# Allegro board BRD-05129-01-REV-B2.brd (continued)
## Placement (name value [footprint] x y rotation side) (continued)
R726  3.01K  [RESC100X50X40]  80.85 41.61 90 bottom
R727  1.50K  [RESC100X50X40]  84.43 40.43 180 bottom
R728  1.50K  [RESC100X50X40]  84.43 46.51 180 bottom
R729  3.01K  [RESC100X50X40]  80.85 45.36 270 bottom
R730  10.0K  [RESC100X50X40]  68.95 48.62 180 top
R731  10.0K  [RESC100X50X40]  68.95 49.51 0 top
R732  10.0K  [RESC100X50X40]  68.95 56.49 180 top
R733  10.0K  [RESC100X50X40]  68.95 57.38 0 top
R734  10.0K  [RESC100X50X40]  68.95 63.92 180 top
R735  10.0K  [RESC100X50X40]  68.95 64.8 0 top
R736  10.0K  [RESC100X50X40]  68.74 39.79 180 top
R737  10.0K  [RESC100X50X40]  68.74 40.67 0 top
R738  30  [RESC100X50X40]  65.99 47.35 180 bottom
R739  30  [RESC100X50X40]  65.99 46.21 180 bottom
R740  30  [RESC100X50X40]  65.99 41.82 180 bottom
R741  30  [RESC100X50X40]  65.99 42.96 180 bottom
R742  30  [RESC100X50X40]  65.99 55.52 180 bottom
R743  30  [RESC100X50X40]  65.99 54.38 180 bottom
R744  30  [RESC100X50X40]  65.99 49.99 180 bottom
R745  30  [RESC100X50X40]  65.99 51.13 180 bottom
R746  30  [RESC100X50X40]  65.99 63.69 180 bottom
R747  30  [RESC100X50X40]  65.99 62.55 180 bottom
R748  30  [RESC100X50X40]  65.99 58.15 180 bottom
R749  30  [RESC100X50X40]  65.99 59.3 180 bottom
R750  30  [RESC100X50X40]  65.99 39.19 180 bottom
R751  30  [RESC100X50X40]  65.99 38.04 180 bottom
R752  30  [RESC100X50X40]  65.99 33.65 180 bottom
R753  30  [RESC100X50X40]  65.99 34.79 180 bottom
R754  10.0K  [RESC100X50X40]  72.56 23.03 180 bottom
R755  22.0  [RESC100X50X40]  53.32 51.59 135 bottom
R756  22.0  [RESC100X50X40]  53.3 50.72 135 top
R757  22.0  [RESC100X50X40]  53.97 53.16 180 bottom
R758  22.0  [RESC100X50X40]  53.94 52.27 180 top
R759  22.0  [RESC100X50X40]  53.32 54.73 225 bottom
R760  22.0  [RESC100X50X40]  53.3 53.82 225 top
R761  1.00K  [RESC100X50X40]  111.68 39.51 0 bottom
R762  40.2K  [RESC100X50X40]  111.68 40.58 0 bottom
R763  10.0K  [RESC100X50X40]  111.68 41.66 180 bottom
R764  100.0K  [RESC100X50X40]  45.13 18.84 270 bottom
R765  100.0K  [RESC100X50X40]  47.16 17.95 270 top
SW1  B3U-1000P  [SW_OMRON_2P]  3.09 78.96 270 top
SW2  B3U-1000P  [SW_OMRON_2P]  3.09 48.69 270 top
TP1  -  [TP_PAD]  20.37 94.41 0 top
TP2  -  [TP_PAD]  11.58 98.55 0 top
TP3  -  [TP_PAD]  26.97 27.61 180 top
TP4  -  [TP_PAD]  4.87 39.29 0 top
TP5  -  [TP_PAD]  25.83 90.98 0 top
TP6  -  [TP_PAD]  49.2 94.15 180 top
TP7  -  [TP_PAD]  7.29 61.9 90 top
TP8  -  [TP_PAD]  50.85 93.26 180 top
TP9  -  [TP_PAD]  74.15 91.06 270 top
TP10  -  [TP_PAD]  77.9 91.99 90 top
TP11  -  [TP_PAD]  54.79 27.7 180 top
TP12  -  [TP_PAD]  70.73 23.69 90 top
TP13  -  [TP_PAD]  76.88 19.1 0 top
TP14  -  [TP_PAD]  130.54 78.89 90 top
TP15  -  [TP_PAD]  80.31 22.02 180 top
TP37  -  [TP_PAD]  8.3 63.42 270 top
TP38  -  [TP_PAD]  8.3 65.07 0 top
TP39  -  [TP_PAD]  8.3 53.13 0 top
TP40  -  [TP_PAD]  96.95 16.3 0 bottom
TP41  -  [TP_PAD]  126.44 45 270 bottom
TP43  -  [TP_PAD]  117.94 57.95 90 bottom
TP45  -  [TP_PAD]  131.26 63.62 270 bottom
TP47  -  [TP_PAD]  20.37 94.41 180 bottom
TP48  -  [TP_PAD]  26.97 27.61 180 bottom
TP49  -  [TP_PAD]  11.58 98.55 180 bottom
TP50  -  [TP_PAD]  4.87 39.29 180 bottom
TP51  -  [TP_PAD]  25.83 90.98 180 bottom
TP52  -  [TP_PAD]  49.2 94.15 180 bottom
TP53  -  [TP_PAD]  7.29 61.9 180 bottom
TP54  -  [TP_PAD]  50.85 93.26 180 bottom
TP55  -  [TP_PAD]  74.15 91.06 180 bottom
TP56  -  [TP_PAD]  77.9 91.99 180 bottom
TP57  -  [TP_PAD]  54.79 27.7 180 bottom
TP58  -  [TP_PAD]  70.73 23.69 180 bottom
TP59  -  [TP_PAD]  76.88 19.1 180 bottom
TP60  -  [TP_PAD]  130.54 78.89 180 bottom
TP61  -  [TP_PAD]  80.31 22.02 180 bottom
TP62  -  [TP_PAD]  18.48 61.51 180 bottom
TP63  -  [TP_PAD]  18.5 60.24 180 bottom
TP64  -  [TP_PAD]  18.59 58.91 180 bottom
TP65  -  [TP_PAD]  18.59 57.58 180 bottom
U1  MPM3840GQV-Z  [PQFN20_MPS_MPM3840GQV]  4.82 55.93 0 bottom
U3  MPM3810AGQB-Z  [QFN12_MPM3805A]  36.06 82.65 270 bottom
U5  MPM3810AGQB-Z  [QFN12_MPM3805A]  26.16 83.69 0 bottom
U6  MP8772  [QFN40P300X300X100-16_MP8772]  17.59 23.99 90 bottom
U7  MP2002A  [DFN300X200X100-8]  6.81 43.53 90 bottom
U8  MP2002A  [DFN300X200X100-8]  75.4 86.18 270 bottom
U9  MP2002A  [DFN300X200X100-8]  60.08 28.49 0 bottom
U11  MP2002A  [DFN300X200X100-8]  41.75 14.97 0 bottom
U12  MP2002A  [DFN300X200X100-8]  63.53 75.26 180 bottom
U13  TPS3430WDRCR  [VSON-CLIP11_3X3MM]  3.65 87.36 90 bottom
U14  INA260  [TSSOP065P620X120_16]  3.96 74.64 90 bottom
U15  M24C64-DRDW8  [TSSOP8_65P440X300MM]  34.17 24.21 90 bottom
U16  PCA9306DCTR  [DCT_R_PDSO_G8]  29.27 25.5 180 top
U19  SLG  [STQFN04P400X400X60_32_270]  34.09 41.67 90 bottom
U22  SN74AVC4T245  [QFN_RSV_16]  38.59 28.66 180 bottom
U24  FT4232HL_LQFP64  [LQFP_64]  55.11 17.71 90 bottom
U25  SN74AVC2T245  [QFN40P140X180X55-10]  48.97 24.75 90 top
U26  93LC56B  [SOIC8P127W390]  66.93 17.86 90 bottom
U37  USB3320  [QFN05P500X500X100_32P_330EP]  43.62 76.96 0 bottom
U38  USB2244-AEZG-06  [QFN05P600X600X85-36_410]  30.88 96.71 0 bottom
U41  MP5016HGQH-Z  [PQFN10_MP5016HGQH]  16.4 96.03 180 top
U42  STMPS2161STR  [SOT95P280X145_5]  4.36 12.75 0 top
U43  USB5744  [VQFN40P700X700X100-56_460EP]  63.78 91.51 0 bottom
U44  GSB311231HR  [CONN_USB_DUAL_GSB311231HR]  49.51 105.52 270 top
U45  MP62341DH-LF-Z  [MSOP8E65P490X110]  39.54 94.77 90 bottom
U64  SN74AVC2T245  [QFN40P140X180X55-10]  43.72 26.08 90 bottom
U66  TPD4E05U06DQAR  [DQA_R_PSON_N10]  44.62 98.09 0 bottom
U67  TPD4E05U06DQAR  [DQA_R_PSON_N10]  52.86 98.41 0 bottom
U82  TPD6E004RSER  [UQFN_8]  30.81 107.44 90 bottom
U89  26MHZ  [OSC_RAL_500X320X154]  4.86 66.13 90 bottom
U91  NB3V1104CDTR2G  [TSSOP8_65P450X310X120]  74.81 80.66 0 bottom
U92  25.000MHz  [OSC_330X260X120_4_RAL]  66.19 79.89 0 bottom
U94  TCAN1043A  [SOIC14_SOT23-THIN_14_DUAL]  110.43 103.54 0 top
U95  ISOW1432BDFMR  [SOIC127P1283X750X355-20]  117.19 88.17 270 top
U96  MP2002A  [DFN300X200X100-8]  54.66 75.94 180 bottom
U97  MPM3810AGQB-Z  [QFN12_MPM3805A]  69.11 26 270 bottom
U98  ADIN1300BCPZ  [LFCSP50P600X600X75_40]  63.78 91.51 180 top
U99  ADIN1300BCPZ  [LFCSP50P600X600X75_40]  96.69 86.15 0 bottom
U100  M24C64-DRDW8  [TSSOP8_65P440X300MM]  54.98 71.36 0 bottom
U101  ADIN1300BCPZ  [LFCSP50P600X600X75_40]  96.69 86.15 180 top
U102  LM5106MM  [VSSOP50P490X110-10]  106.6 37 90 top
U103  LM5106MM  [VSSOP50P490X110-10]  106.6 53.89 90 top
U104  LM5106MM  [VSSOP50P490X110-10]  106.09 70.79 90 top
U105  INA241XX  [SOT23_290X160X110_8]  123.31 38.15 270 bottom
U106  INA241XX  [SOT23_290X160X110_8]  123.95 48.18 270 bottom
U107  INA241XX  [SOT23_290X160X110_8]  123.95 57.32 270 bottom
U108  AD7352  [TSSOP065P620X120_16]  60.86 44.59 180 bottom
U109  SN74AVC4T245  [QFN_RSV_16]  49.71 52.75 270 bottom
U110  AD7352  [TSSOP065P620X120_16]  60.86 52.75 180 bottom
U111  SN74AVC4T245  [QFN_RSV_16]  49.71 46.69 270 bottom
U112  AD7352  [TSSOP065P620X120_16]  60.86 60.92 180 bottom
U113  INA241XX  [SOT23_290X160X110_8]  112.28 26.91 90 bottom
U114  AD7352  [TSSOP065P620X120_16]  60.86 36.42 180 bottom
U115  SN74AVC4T245  [QFN_RSV_16]  52.37 41.3 270 bottom
U116  TXU0104PWR  [TSSOP65P440X500X120_14]  124.62 71.94 180 top
U117  AM26LV32E  [SOIC127P600X175-16]  121.84 92.63 0 bottom
U118  SN74AVC2T245  [QFN40P140X180X55-10]  84.59 17 90 bottom
U119  AD7797B  [TSSOP065P620X120_16]  91.99 14.51 180 bottom
U120  SN74AVC2T245  [QFN40P140X180X55-10]  80.28 16.88 90 bottom
U121  UCC27516DRS  [SON95P300X300X80-6TP]  107.12 15.52 270 top
U122  MP2002A  [DFN300X200X100-8]  72.89 16.63 180 bottom
U123  TLV9102IDDFR  [SOT65P280X280X110-8]  70.76 47.93 90 bottom
U124  TLV9102IDDFR  [SOT65P280X280X110-8]  70.76 55.8 90 bottom
U125  TLV9102IDDFR  [SOT65P280X280X110-8]  70.76 63.23 90 bottom
U127  LTC6362IDD#PBF  [DFN300X300X80-8]  75.99 51.87 90 bottom
U128  LTC6362IDD#PBF  [DFN300X300X80-8]  83.23 52.17 90 bottom
U129  LTC6362IDD#PBF  [DFN300X300X80-8]  75.99 60.81 90 bottom
U130  LTC6362IDD#PBF  [DFN300X300X80-8]  83.23 61.12 90 bottom
U131  LTC6362IDD#PBF  [DFN300X300X80-8]  75.99 69.76 90 bottom
U132  LTC6362IDD#PBF  [DFN300X300X80-8]  83.23 70.07 90 bottom
U133  LTC6362IDD#PBF  [DFN300X300X80-8]  75.99 42.92 90 bottom
U134  LTC6362IDD#PBF  [DFN300X300X80-8]  83.23 43.48 90 bottom
U135  TLV9102IDDFR  [SOT65P280X280X110-8]  120.82 42.41 180 bottom
U136  TLV9102IDDFR  [SOT65P280X280X110-8]  124.63 62.02 180 bottom
U137  TLV9102IDDFR  [SOT65P280X280X110-8]  70.55 39.1 90 bottom
X1  TPD4S012  [DRY_6_SON]  55.85 8 0 top
X2  12.00MHZ  [XTAL_320X250X71]  61.93 9.2 0 bottom
X5  TPD4S012  [DRY_6_SON]  49.73 98.09 0 bottom
X6  TPD4S012  [DRY_6_SON]  47.42 98.09 0 bottom
X11  24.00MHZ  [XTAL_EPSON_FA238]  31.19 88.4 180 bottom
X12  24.00MHZ  [XTAL_EPSON_FA238]  47.54 69.22 180 bottom
X13  25MHZ  [XTAL_EPSON_FA238]  59.58 82.05 0 bottom
X14  25.00MHZ  [XTAL_ABM8]  73.59 94.51 0 top
Z1  -  [0201_SHORT]  15.15 19.98 0 bottom
Z4  -  [0201_SHORT]  33.69 83.75 270 bottom
Z5  -  [0201_SHORT]  25.06 81.32 0 bottom
Z6  -  [0201_SHORT]  66.35 26.97 270 bottom

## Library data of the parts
C1-C3 C6 C26 C30-C35 C311 C312 = CAP_NP: signal model: DEFAULT_CAPACITOR_2.2e+07pF_2_1
C4 C353 C354 = CAP_NP: alternate symbols: (CAPC200X125X125RND); signal model: DEFAULT_CAPACITOR_4.7e+07pF_2_1
C5 C103 C104 = CAP_NP: alternate symbols: (CAPC100X50X55RND); signal model: DEFAULT_CAPACITOR_27.000000pF_2_1
C7 C8 C24 C25 = CAP_NP: alternate symbols: (0603); signal model: DEFAULT_CAPACITOR_2.2e+07pF_2_1
C14 C21 C27 C41 C44 C295-C298 = CAP_NP: alternate symbols: (CAPC100X50X55RND); signal model: DEFAULT_CAPACITOR_1000pF_2_1
C16 C17 C22 C23 C28 C29 C42 C43 C78 C79 C203 C204 C272 C274 = CAP_NP: signal model: DEFAULT_CAPACITOR_1e+07pF_2_1
C36 C37 C49 C50 C53 C64 C75 C80 C81 C83 C84 C87 C88 C90-C94 C96-C102 C105 C175 C176 C207 C209 C210 C234 C236 C237 C273 C275-C277 C279-C286 C289-C292 C299 C300 C303 C304 C309 C310 C315-C317 C324 C329 = CAP_NP: alternate symbols: (CAPC100X50X55RND); signal model: DEFAULT_CAPACITOR_100000pF_2_1
C38 C51 C89 C205 C208 C238 C323 = CAP_NP: alternate symbols: (CAPC100X50X55RND); signal model: DEFAULT_CAPACITOR_1e+06pF_2_1
C39 = CAP_NP: alternate symbols: (CAPC100X50X55RND); signal model: DEFAULT_CAPACITOR_56.000000pF_2_1
C40 = CAP_NP: signal model: DEFAULT_CAPACITOR_22000pF_2_1
C52 = CAP_NP: alternate symbols: ((0402,C402-25,CAPC100X50X55L25NRND,CAPC100X50X55L30NRND,CAPC100X50X55L30N)); signal model: DEFAULT_CAPACITOR_220000pF_2_1
C73 = CAP_NP: alternate symbols: (CAPC100X50X55RND); signal model: DEFAULT_CAPACITOR_100.000000pF_2_1
C82 C85 C95 = CAP_NP: alternate symbols: (CAPC100X50X60RND); signal model: DEFAULT_CAPACITOR_4.7e+06pF_2_1
C206 = CAP_NP: signal model: DEFAULT_CAPACITOR_47000pF_2_1
C235 = CAP_NP: alternate symbols: (CAPC100X50X55RND); signal model: DEFAULT_CAPACITOR_39.000000pF_2_1
C278 = CAP_NP: alternate symbols: (CAPC100X50X55RND); signal model: DEFAULT_CAPACITOR_2.2e+06pF_2_1
C319 = CAP_NP: alternate symbols: ((0402,C402-25,CAPC100X50X55L25NRND,CAPC100X50X55L30NRND,CAPC100X50X55L30N)); signal model: DEFAULT_CAPACITOR_6800pF_2_1
C344 = CAP_NP: alternate symbols: (CAPC100X50X56RND); signal model: DEFAULT_CAPACITOR_33.000000pF_2_1
C369 C548 C558-C565 C568 C569 C581 C582 C589 C591 C592 C598-C603 C606-C609 C612 C619-C629 C631 C632 C634-C638 C640 C642 C645-C652 C654-C656 C658 C659 C661-C663 C665-C674 C676-C678 C680 C681 C683-C685 C687 C693-C695 C701 C702 C708-C715 C717-C720 C722 C723 C725 C726 C728 C729 C731-C734 C736-C738 C741-C743 C745-C747 C753-C756 C758 C759 C761-C769 C771-C783 C785 C788 C789 C793-C825 = CAP_NP: alternate symbols: (CAPC100X50X55RND)
C370 C371 = CAP_NP: alternate symbols: (CAPC100X50X56RND)
C372-C380 C688 C696 C703 C828 C829 = CAP_NP: alternate symbols: ((0402,C402-25,CAPC100X50X55L25NRND,CAPC100X50X55L30NRND,CAPC100X50X55L30N))
C387 C604 C605 C610 C611 C613-C618 C630 C633 C641 C653 C657 C660 C675 C679 C682 C689-C692 C697-C700 C704-C707 C716 C721 C724 C727 C730 C735 C739 C740 C744 C748-C750 C752 C757 C760 C770 C784 C786 C787 C826 C827 = CAP_NP
C557 C574 = CAP_NP: alternate symbols: (CAPC100X50X60RND)
C566 C567 C643 C644 = CAP_NP: alternate symbols: (CAPC100X50X50RND)
C751 = CAP_P
D1 D12 = DIODE_ZENER
D2 = BAT54T1G
D3-D5 = MBRS260T3G
D15-D20 = TVS_RCLAMP0502BATCT
D21 = DIODE_TVS_UDIR
D22 D23 = TVS_SM712-02HTG
D24 D25 = SCHOTTKY_DIODE
DS1-DS10 = LED
F1 = ITV5432
J1 J19-J21 J44 = HDR_1X3
J2 = HDR_2X6
J3 = HDR_2X7
J4 = CONN_USB_MICRO_B_TH
J11 = 5025700893
J12 = PJ-202AH
J13 = HDR_REMOTE_SENSE_A: signal model: DEFAULT_RESISTOR_22.000000OHM_2_1
J15-J17 J26 J28 J30 J40 J41 = TP-HOOK: alternate symbols: (TP_KEY_MINI_DNP)
J18 J46 J47 = EM_3PIN
J22 J45 = EM1935187_ST
J23 J51 = HDR_1X2
J24 = HFJ11_1G01E_L12RL
J25 = 0879-2C1R-54
J27 J29 J31 J52-J54 = TEST_LOOP_5016
J32 = MR60PB-M
J39 = XT60PT-M
J42 = SHROUDED_HDR_1X6
J43 = HDR_2X5
JA1 = SAMTEC-ADx6-60X4
JA3 = SAMTEC-ADx6-10X4
L1 = IND: signal model: DEFAULT_INDUCTOR_1200nH_2_1
L2-L5 L8-L17 = IND
MH1-MH10 = HOLE
Q5 = IRFHS8342
Q6-Q10 Q12 Q13 Q17 Q19-Q23 Q26-Q34 Q37 Q43-Q48 = DMN26D0UFB4
Q18 = FET-3PIN
Q24 Q25 = FDN304P
Q35 Q36 Q38-Q42 = FET_NCH_DFN5
R1 R54 R219 R220 = RES: signal model: DEFAULT_RESISTOR_200000OHM_2_1
R2 = RES: alternate symbols: (0402); signal model: DEFAULT_RESISTOR_44200OHM_2_1
R4 R5 R7 R28 = RES: signal model: DEFAULT_RESISTOR_100000OHM_2_1
R6 R17 R23 R29 R38 R40 R41 R45-R51 R74 R76 R77 R209 R210 R218 R233-R235 R241 R260-R263 = RES: alternate symbols: (RESC100X50X40RND); signal model: DEFAULT_RESISTOR_10000OHM_2_1
R14 = RES: signal model: DEFAULT_RESISTOR_68000OHM_2_1
R16 = RES: alternate symbols: ((0402,C402-25,RESC100X50X40L25NRND)); signal model: DEFAULT_RESISTOR_34000OHM_2_1
R21 R26 = RES: alternate symbols: (RESC100X50X40RND); signal model: DEFAULT_RESISTOR_40200OHM_2_1
R24 = RES: alternate symbols: (RESC100X50X40RND); signal model: DEFAULT_RESISTOR_26100OHM_2_1
R27 = RES: alternate symbols: (RESC100X50X40RND); signal model: DEFAULT_RESISTOR_45300OHM_2_1
R30 = RES: alternate symbols: (RESC100X50X40RND); signal model: DEFAULT_RESISTOR_20000OHM_2_1
R31 = RES: alternate symbols: ((0402,C402-25,RESC100X50X40L25NRND)); signal model: DEFAULT_RESISTOR_2700OHM_2_1
R32 R75 R256 = RES: alternate symbols: (RESC100X50X40RND); signal model: DEFAULT_RESISTOR_1000.000000OHM_2_1
R33 = RES: signal model: DEFAULT_RESISTOR_0.001OHM_2_1
R34 = RES: alternate symbols: (RESC60X30X26RND); signal model: DEFAULT_RESISTOR_100000OHM_2_1
R36 R39 = RES: signal model: DEFAULT_RESISTOR_56200OHM_2_1
R44 R66 R222 = RES: alternate symbols: (RESC100X50X40RND); signal model: DEFAULT_RESISTOR_0.001OHM_2_1
R55 R56 = RES: alternate symbols: ((0402,C402-25,RESC100X50X40L25NRND)); signal model: DEFAULT_RESISTOR_2210OHM_2_1
R58 R61 R63 R64 R452 R466 R467 R473 R474 R517 R518 R520 R522 R524 R525 R536 R537 R540 R563 R564 R592 R593 R617 R626 R632 R638-R642 R647 R648 R651 R652 R659-R661 R684 R707 R708 R711 R712 R715 R716 R719 R720 R723 R724 R727 R728 R738-R753 = RES
R78 = RES: alternate symbols: (RESC100X50X40RND); signal model: DEFAULT_RESISTOR_2000OHM_2_1
R79 R221 = RES: alternate symbols: (RESC100X50X40RND); signal model: DEFAULT_RESISTOR_12000OHM_2_1
R130 = RES: alternate symbols: (RESC100X50X40RND); signal model: DEFAULT_RESISTOR_4700OHM_2_1
R133 = RES: alternate symbols: ((0402,C402-25,RESC100X50X40L25NRND)); signal model: DEFAULT_RESISTOR_300000OHM_2_1
R134 = RES: signal model: DEFAULT_RESISTOR_274000OHM_2_1
R135 = RES: signal model: DEFAULT_RESISTOR_422.000000OHM_2_1
R157-R161 R254 = RES: alternate symbols: (RESC100X50X40RND); signal model: DEFAULT_RESISTOR_261.000000OHM_2_1
R162-R165 = RES: alternate symbols: (RESC100X50X40RND); signal model: DEFAULT_RESISTOR_499.000000OHM_2_1
R166 R167 R243 = RES: alternate symbols: (RESC100X50X40RND); signal model: DEFAULT_RESISTOR_100000OHM_2_1
R213 = RES: alternate symbols: (RESC100X50X40RND); signal model: DEFAULT_RESISTOR_8060OHM_2_1
R223 = RES: signal model: DEFAULT_RESISTOR_1.000000OHM_2_1
R248-R253 = RES: signal model: DEFAULT_CAPACITOR_100000pF_2_1
R264 = RES: alternate symbols: (RESC100X50X40RND); signal model: DEFAULT_RESISTOR_20.000000OHM_2_1
R265 = RES: alternate symbols: (RESC60X30X26RND)
R266 R267 R619 R621 R628 R629 R634 R635 R764 R765 = RES: alternate symbols: (0402)
R274 R275 R294 R295 R428 R429 R446-R451 R463-R465 R468 R469 R471 R472 R477-R480 R494 R495 R500 R501 R507 R514-R516 R519 R521 R523 R526-R534 R538 R541-R561 R565 R567-R578 R581-R590 R594 R596-R616 R618 R620 R623-R625 R627 R630 R631 R633 R636 R637 R643 R646 R649 R650 R653 R656 R662 R663 R667 R669-R683 R685 R754 R761-R763 = RES: alternate symbols: (RESC100X50X40RND)
R276-R283 = RES: alternate symbols: (RESC100X50X40RND); signal model: DEFAULT_CAPACITOR_100000pF_2_1
R462 R539 R566 R579 R580 R595 R622 R664-R666 R668 R702-R706 R709 R710 R713 R714 R717 R718 R721 R722 R725 R726 R729-R737 = RES: alternate symbols: ((0402,C402-25,RESC100X50X40L25NRND))
R755-R760 = RES: alternate symbols: ((0402,C402-25,RESC100X50X40L25NRND)); signal model: RES_RESC100X50X40_22.0_(0402_C402-25_RESC100X50X40L25NRND)_22.0
SW1 SW2 = BTN_MOMENT
TP1-TP15 TP37-TP41 TP43 TP45 TP47-TP65 = TP
U1 = MPM3840
U3 U5 U97 = MPM3810A
U6 = MP8771: alternate symbols: (QFN40P300X300X100-16)
U7-U9 U11 U12 U96 U122 = MP8904: alternate symbols: (QFN_MP8904DD_8)
U13 = TPS3430
U14 = INA260AIPW
U15 U100 = M24C64
U16 = PCA9306DCTR
U19 = SLG
U22 U109 U111 U115 = SN74AVC4T245
U24 = FT4232HL
U25 U64 U118 U120 = SN74AVC2T245
U26 = 93LC56B
U37 = USB3320_QFN32
U38 = USB2244
U41 = MP5016H
U42 = TPS2065CDBVT
U43 = USB5744
U44 = GSB311231HR
U45 = MP62341DH
U66 U67 = TPD4E05U06DQAR
U82 = TPD6E004RSER
U89 = XCO583IV11-27.000
U91 = NB3V1104CDTR2G
U92 = SIT_4PIN
U94 = TCAN1043A
U95 = ISOW1432BDFMR
U98 U99 U101 = ADIN1300BCPZ
U102-U104 = LM5106MM
U105-U107 U113 = INA241XX
U108 U110 U112 U114 = AD7352
U116 = TXU0104PWR
U117 = AM26LV32E
U119 = AD7797B
U121 = UCC27516DRS
U123-U125 U135-U137 = TLV9102IDDF
U127-U134 = LTC6362
X1 X5 X6 = TPD4S012
X2 X14 = ABM8_XTAL
X11 X12 = FA-238A_XTAL
X13 = FA238
Z1 Z4-Z6 = 0201_SHORT

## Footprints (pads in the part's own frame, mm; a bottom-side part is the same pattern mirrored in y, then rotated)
0201_SHORT
  rect 0.381x0.381 smd: 1(-0.292,0)
  custom 0.089x0.089 smd: 2(0.292,0)
87832_1420
  round 1.016 hole 1.016 unplated: (-5,0) (5,0)
  rect 1x2.75 smd: 1(-6,-2.125) 2(-6,2.125) 3(-4,-2.125) 4(-4,2.125) 5(-2,-2.125) 6(-2,2.125) 7(0,-2.125) 8(0,2.125) 9(2,-2.125) 10(2,2.125) 11(4,-2.125) 12(4,2.125) 13(6,-2.125) 14(6,2.125)
AMASS_XT60PW-M
  rect 3.7x3.7 hole 2.692: 1(0,0)
  round 3.7 hole 2.692: 2(-7.2,0)
  oval 1.2x2.7 hole 0.6x1.7: M1(3.15,6) M2(-10.35,6)
BEL_0879-2C1R-54
  round 3.25 hole 3.251 unplated: (-2.407,-4.699) (9.023,-4.699)
  round 2.51 hole 1.575: 1(-5.199,10.791) 2(-5.197,-9.269) 3(11.813,-9.269) 4(11.813,6.731)
  round 1.5 hole 0.889: P1_L(0,0) P1_U(6.61,0) P2_L(1.27,1.27) P2_U(5.34,1.27) P3_L(0,2.54) P3_U(6.61,2.54) P4_L(1.27,3.81) P4_U(5.34,3.81) P5_L(0,5.08) P5_U(6.61,5.08) P6_L(1.27,6.35) P6_U(5.34,6.35) P7_L(0,7.62) P7_U(6.61,7.62) P8_L(1.27,8.89) P8_U(5.34,8.89) P9_L(0,10.16) P9_U(6.61,10.16) P10_L(1.276,11.43) P10_U(5.34,11.43)
  round 1.52 hole 1.016: P11_L2_U(-3.677,7.091) P11_L4_L(-3.677,-7.599) P12_L2_U(-3.677,0.741) P12_L4_L(-1.137,-7.599) P13_L1_U(10.294,3.281) P13_L3_L(7.753,-7.599) P14_L1_U(10.294,0.741) P14_L3_L(10.293,-7.599)
CAPC100X50X50
  rect 0.5x0.51 smd: 1(-0.45,0) 2(0.45,0)
CAPC100X50X55
  rect 0.5x0.51 smd: 1(-0.45,0) 2(0.45,0)
CAPC100X50X56
  rect 0.5x0.51 smd: 1(-0.45,0) 2(0.45,0)
CAPC100X50X60
  rect 0.5x0.51 smd: 1(-0.45,0) 2(0.45,0)
CAPC100X50X70
  rect 0.5x0.51 smd: 1(-0.45,0) 2(0.45,0)
CAPC160X80X100
  rect 0.71x0.81 smd: 1(-0.645,0) 2(0.645,0)
CAPC200X125X125
  rect 0.98x1.32 smd: 1(-0.78,0) 2(0.78,0)
CAPC200X125X145
  rect 0.98x1.32 smd: 1(-0.78,0) 2(0.78,0)
CAPC620X540X280
  rect 1.27x5.654 smd: 1(-2.687,0) 2(2.687,0)
CAPE_1250X2000
  rect 1.524x1.524 hole 0.914: 1(0,0)
  round 1.524 hole 0.914: 2(5,0)
CON_AMASS_MR60PB-M
  rect 4.6x4.6 hole 3.404: 1(0,0)
  round 4.6 hole 3.404: 2(5.5,0) 3(11,0)
CON_CUI_PJ202AH
  oval 1.5x4.6 hole 1.016x3.505: 1(0,0)
  oval 1.5x3.8 hole 1.016x2.997: 2(6,0)
  oval 3.8x1.5 hole 2.997x1.016: 3(3,4.7)
CON_ETH_HFJ111G01E_L12RL
  round 3.25 hole 3.251 unplated: (-5.715,0) (5.715,0)
  round 1.27 hole 0.889: 1(-5.715,8.89) 2(-4.445,6.35) 3(-3.175,8.89) 4(-1.905,6.35) 5(-0.635,8.89) 6(0.635,6.35) 7(1.905,8.89) 8(3.175,6.35) 9(4.445,8.89) 10(5.715,6.35)
  round 1.52 hole 1.016: 11(-6.629,-4.064) 12(-4.089,-4.064) 13(4.089,-4.064) 14(6.629,-4.064)
  round 2.1 hole 1.6: 15(-7.747,3.048) 16(7.747,3.048)
CON_EUROMAG_ST_4_5MM
  rect 2.2x2.2 hole 1.422: 1(0,0)
  round 2.2 hole 1.422: 2(0,-5) 3(0,-10) 4(0,-15)
CON_HR_ZX62D_AB_5P8
  rect 0.4x1.35 smd: 1(-1.3,0) 2(-0.65,0) 3(0,0) 4(0.65,0) 5(1.3,0)
  oval 1.23x1.9 hole 0.813x1.499: 6(4.089,-2.802) 9(-4.089,-2.802)
  rect 1.8x1.9 smd: 7(1.156,-2.802) 8(-1.156,-2.802)
  oval 1.05x1.25 hole 0.66x0.838: 10(-2.226,0.323) 11(2.226,0.323)
CON_MOL_10P_5025700893
  rect 0.8x1.5 smd: 1(0,0) 2(1.1,0) 3(2.2,0) 4(3.3,0) 5(4.4,0) 6(5.5,0) 7(6.6,0) 8(7.7,0)
  rect 1.4x1.7 smd: 9(-3.747,2.896) 10(9.157,2.896)
  rect 1.15x1.5 smd: 11(9.157,-6.871)
  rect 1.5x1.15 smd: 12(8.712,-11.582) 13(2.095,-11.582) 14(-0.191,-11.582)
CON_SAMTEC_ADM6_10_4
  round 0.95 hole 0.95 unplated: (-4.26,1.27) (4.26,0)
  round 0.356 smd: A1(2.857,1.75) A2(2.223,1.75) A3(1.587,1.75) A4(0.953,1.75) A5(0.318,1.75) A6(-0.318,1.75) A7(-0.953,1.75) A8(-1.587,1.75) A9(-2.223,1.75) A10(-2.857,1.75) B1(2.857,0.79) B2(2.223,0.79) B3(1.587,0.79) B4(0.953,0.79) B5(0.318,0.79) B6(-0.318,0.79) B7(-0.953,0.79) B8(-1.587,0.79) B9(-2.223,0.79) B10(-2.857,0.79) C1(2.857,-0.79) C2(2.223,-0.79) C3(1.587,-0.79) C4(0.953,-0.79) C5(0.318,-0.79) C6(-0.318,-0.79) C7(-0.953,-0.79) C8(-1.587,-0.79) C9(-2.223,-0.79) C10(-2.857,-0.79) D1(2.857,-1.75) D2(2.223,-1.75) D3(1.587,-1.75) D4(0.953,-1.75) D5(0.318,-1.75) D6(-0.318,-1.75) D7(-0.953,-1.75) D8(-1.587,-1.75) D9(-2.223,-1.75) D10(-2.857,-1.75)
CON_SAMTEC_ADM6_60_4
  round 0.95 hole 0.95 unplated: (-20.135,1.27) (20.135,0)
  round 0.356 smd: A1(18.733,1.75) A2(18.098,1.75) A3(17.462,1.75) A4(16.828,1.75) A5(16.192,1.75) A6(15.557,1.75) A7(14.922,1.75) A8(14.287,1.75) A9(13.652,1.75) A10(13.018,1.75) A11(12.383,1.75) A12(11.748,1.75) A13(11.113,1.75) A14(10.477,1.75) A15(9.842,1.75) A16(9.207,1.75) A17(8.572,1.75) A18(7.938,1.75) A19(7.303,1.75) A20(6.668,1.75) A21(6.032,1.75) A22(5.397,1.75) A23(4.763,1.75) A24(4.128,1.75) A25(3.493,1.75) A26(2.857,1.75) A27(2.223,1.75) A28(1.587,1.75) A29(0.953,1.75) A30(0.318,1.75) A31(-0.318,1.75) A32(-0.953,1.75) A33(-1.587,1.75) A34(-2.223,1.75) A35(-2.857,1.75) A36(-3.493,1.75) A37(-4.128,1.75) A38(-4.763,1.75) A39(-5.397,1.75) A40(-6.032,1.75) A41(-6.668,1.75) A42(-7.303,1.75) A43(-7.938,1.75) A44(-8.572,1.75) A45(-9.207,1.75) A46(-9.842,1.75) A47(-10.477,1.75) A48(-11.113,1.75) A49(-11.748,1.75) A50(-12.383,1.75) A51(-13.018,1.75) A52(-13.652,1.75) A53(-14.287,1.75) A54(-14.922,1.75) A55(-15.557,1.75) A56(-16.192,1.75) A57(-16.828,1.75) A58(-17.462,1.75) A59(-18.098,1.75) A60(-18.733,1.75) B1(18.733,0.79) B2(18.098,0.79) B3(17.462,0.79) B4(16.828,0.79) B5(16.192,0.79) B6(15.557,0.79) B7(14.922,0.79) B8(14.287,0.79) B9(13.652,0.79) B10(13.018,0.79) B11(12.383,0.79) B12(11.748,0.79) B13(11.113,0.79) B14(10.477,0.79) B15(9.842,0.79) B16(9.207,0.79) B17(8.572,0.79) B18(7.938,0.79) B19(7.303,0.79) B20(6.668,0.79) B21(6.032,0.79) B22(5.397,0.79) B23(4.763,0.79) B24(4.128,0.79) B25(3.493,0.79) B26(2.857,0.79) B27(2.223,0.79) B28(1.587,0.79) B29(0.953,0.79) B30(0.318,0.79) B31(-0.318,0.79) B32(-0.953,0.79) B33(-1.587,0.79) B34(-2.223,0.79) B35(-2.857,0.79) B36(-3.493,0.79) B37(-4.128,0.79) B38(-4.763,0.79) B39(-5.397,0.79) B40(-6.032,0.79) B41(-6.668,0.79) B42(-7.303,0.79) B43(-7.938,0.79) B44(-8.572,0.79) B45(-9.207,0.79) B46(-9.842,0.79) B47(-10.477,0.79) B48(-11.113,0.79) B49(-11.748,0.79) B50(-12.383,0.79) B51(-13.018,0.79) B52(-13.652,0.79) B53(-14.287,0.79) B54(-14.922,0.79) B55(-15.557,0.79) B56(-16.192,0.79) B57(-16.828,0.79) B58(-17.462,0.79) B59(-18.098,0.79) B60(-18.733,0.79) C1(18.733,-0.79) C2(18.098,-0.79) C3(17.462,-0.79) C4(16.828,-0.79) C5(16.192,-0.79) C6(15.557,-0.79) C7(14.922,-0.79) C8(14.287,-0.79) C9(13.652,-0.79) C10(13.018,-0.79) C11(12.383,-0.79) C12(11.748,-0.79) C13(11.113,-0.79) C14(10.477,-0.79) C15(9.842,-0.79) C16(9.207,-0.79) C17(8.572,-0.79) C18(7.938,-0.79) C19(7.303,-0.79) C20(6.668,-0.79) C21(6.032,-0.79) C22(5.397,-0.79) C23(4.763,-0.79) C24(4.128,-0.79) C25(3.493,-0.79) C26(2.857,-0.79) C27(2.223,-0.79) C28(1.587,-0.79) C29(0.953,-0.79) C30(0.318,-0.79) C31(-0.318,-0.79) C32(-0.953,-0.79) C33(-1.587,-0.79) C34(-2.223,-0.79) C35(-2.857,-0.79) C36(-3.493,-0.79) C37(-4.128,-0.79) C38(-4.763,-0.79) C39(-5.397,-0.79) C40(-6.032,-0.79) C41(-6.668,-0.79) C42(-7.303,-0.79) C43(-7.938,-0.79) C44(-8.572,-0.79) C45(-9.207,-0.79) C46(-9.842,-0.79) C47(-10.477,-0.79) C48(-11.113,-0.79) C49(-11.748,-0.79) C50(-12.383,-0.79) C51(-13.018,-0.79) C52(-13.652,-0.79) C53(-14.287,-0.79) C54(-14.922,-0.79) C55(-15.557,-0.79) C56(-16.192,-0.79) C57(-16.828,-0.79) C58(-17.462,-0.79) C59(-18.098,-0.79) C60(-18.733,-0.79) D1(18.733,-1.75) D2(18.098,-1.75) D3(17.462,-1.75) D4(16.828,-1.75) D5(16.192,-1.75) D6(15.557,-1.75) D7(14.922,-1.75) D8(14.287,-1.75) D9(13.652,-1.75) D10(13.018,-1.75) D11(12.383,-1.75) D12(11.748,-1.75) D13(11.113,-1.75) D14(10.477,-1.75) D15(9.842,-1.75) D16(9.207,-1.75) D17(8.572,-1.75) D18(7.938,-1.75) D19(7.303,-1.75) D20(6.668,-1.75) D21(6.032,-1.75) D22(5.397,-1.75) D23(4.763,-1.75) D24(4.128,-1.75) D25(3.493,-1.75) D26(2.857,-1.75) D27(2.223,-1.75) D28(1.587,-1.75) D29(0.953,-1.75) D30(0.318,-1.75) D31(-0.318,-1.75) D32(-0.953,-1.75) D33(-1.587,-1.75) D34(-2.223,-1.75) D35(-2.857,-1.75) D36(-3.493,-1.75) D37(-4.128,-1.75) D38(-4.763,-1.75) D39(-5.397,-1.75) D40(-6.032,-1.75) D41(-6.668,-1.75) D42(-7.303,-1.75) D43(-7.938,-1.75) D44(-8.572,-1.75) D45(-9.207,-1.75) D46(-9.842,-1.75) D47(-10.477,-1.75) D48(-11.113,-1.75) D49(-11.748,-1.75) D50(-12.383,-1.75) D51(-13.018,-1.75) D52(-13.652,-1.75) D53(-14.287,-1.75) D54(-14.922,-1.75) D55(-15.557,-1.75) D56(-16.192,-1.75) D57(-16.828,-1.75) D58(-17.462,-1.75) D59(-18.098,-1.75) D60(-18.733,-1.75)
CONN_USB_DUAL_GSB311231HR
  round 1.1 hole 0.711: 1(-1.5,3.5) 2(-1.5,1) 3(-1.5,-1) 4(-1.5,-3.5) 5(0,-4) 6(0,-2) 7(0,0) 8(0,2) 9(0,4) 10(1.7,3.5) 11(1.7,1) 12(1.7,-1) 13(1.7,-3.5) 14(3.2,-4) 15(3.2,-2) 16(3.2,0) 17(3.2,2) 18(3.2,4)
  round 3.1 hole 2.311: 19(-3.5,-6.57) 20(2.18,-6.57) 21(2.18,6.57) 22(-3.5,6.57)
DCT_R_PDSO_G8
  rect 0.3x1.6 smd: 1(-0.975,-1.7) 2(-0.325,-1.7) 3(0.325,-1.7) 4(0.975,-1.7) 5(0.975,1.7) 6(0.325,1.7) 7(-0.325,1.7) 8(-0.975,1.7)
DFN300X200X100-8
  rect 0.7x0.3 smd: 1(-1.45,0.75) 2(-1.45,0.25) 3(-1.45,-0.25) 4(-1.45,-0.75) 5(1.45,-0.75) 6(1.45,-0.25) 7(1.45,0.25) 8(1.45,0.75)
  rect 1.7x1.6 smd: 9(0,0)
DFN300X300X80-8
  rect 0.75x0.3 smd: 1(-1.425,0.75) 2(-1.425,0.25) 3(-1.425,-0.25) 4(-1.425,-0.75) 5(1.425,-0.75) 6(1.425,-0.25) 7(1.425,0.25) 8(1.425,0.75)
  rect 1.7x2.5 smd: 9(0,0)
DFN_105X65X40_3
  rect 0.4x0.25 smd: 1(-0.35,0.225) 2(-0.35,-0.225)
  rect 0.4x0.7 smd: 3(0.35,0)
DIO_SMB_403A_03
  rect 2.16x2.74 smd: 1(-2.21,0) 2(2.21,0)
DIOC100X60X45
  rect 0.6x0.5 smd: 1(-0.5,0) 2(0.5,0)
DO_214AC
  rect 2.1x1.8 smd: 1(-2.2,0) 2(2.2,0)
DQA_R_PSON_N10
  rect 0.3x0.55 smd: 1(-1,-0.385) 2(-0.5,-0.385) 4(0.5,-0.385) 5(1,-0.385) 6(1,0.385) 7(0.5,0.385) 9(-0.5,0.385) 10(-1,0.385)
  rect 0.4x0.55 smd: 3(0,-0.385) 8(0,0.385)
DRY_6_SON
  rect 0.3x0.52 smd: 1(-0.5,-0.385) 2(0,-0.385) 3(0.5,-0.385) 4(0.5,0.385) 5(0,0.385) 6(-0.5,0.385)
FUSE_ITV5432L5030WR
  rect 2.4x1.4 smd: 1(0,-1.4) 3(0,1.4)
  rect 1.25x1.9 smd: 2(-2.575,0.25) 4(2.575,0.25)
FUSE_LITTLEFUSE_50SMDJ_33A
  rect 2.4x3.48 smd: 1(-3.3,0) 2(3.3,0)
HDR_1X2
  rect 1.524x1.524 hole 1.118: 1(0,0)
  round 1.524 hole 1.118: 2(2.54,0)
HDR_1X2_LOCK_MOLEX
  rect 1.524x1.524 hole 1.118: 1(0,0)
  round 1.524 hole 1.118: 2(2.54,0)
HDR_1X3
  rect 1.524x1.524 hole 1.118: 1(0,0)
  round 1.524 hole 1.118: 2(2.54,0) 3(5.08,0)
HDR_2X5
  rect 1.524x1.524 hole 1.016: 1(0,0)
  round 1.52 hole 1.016: 2(0,2.54) 3(2.54,0) 4(2.54,2.54) 5(5.08,0) 6(5.08,2.54) 7(7.62,0) 8(7.62,2.54) 9(10.16,0) 10(10.16,2.54)
HDR_F2X6_PMOD
  rect 1.626x1.626 hole 1.118: 1(6.35,2.54)
  round 1.626 hole 1.118: 2(6.35,0) 3(3.81,2.54) 4(3.81,0) 5(1.27,2.54) 6(1.27,0) 7(-1.27,2.54) 8(-1.27,0) 9(-3.81,2.54) 10(-3.81,0) 11(-6.35,2.54) 12(-6.35,0)
HDR_TE_1X6_100P
  rect 1.8x1.8 hole 1.067: 1(0,0)
  round 1.8 hole 1.067: 2(-2.54,0) 3(-5.08,0) 4(-7.62,0) 5(-10.16,0) 6(-12.7,0)
IND_COIL_XEL5030
  rect 1.18x4.7 smd: 1(-1.655,0) 2(1.655,0)
INDC160X80X95
  rect 0.71x0.81 smd: 1(-0.645,0) 2(0.645,0)
INDC160X80X95_MURATA
  rect 0.8x1.05 smd: 1(-0.6,0) 2(0.6,0)
INDC200X125X110
  rect 0.98x1.32 smd: 1(-0.78,0) 2(0.78,0)
INDC_MURATA100X50X50
  rect 0.5x0.64 smd: 1(-0.45,0) 2(0.45,0)
LED_0603
  rect 0.71x0.81 smd: 1(-0.645,0) 2(0.645,0)
LED_0805
  rect 0.98x1.32 smd: 1(-0.78,0) 2(0.78,0)
LFCSP50P600X600X75_40
  rrect 0.8x0.3 smd: 1(-2.85,2.25) 10(-2.85,-2.25) 21(2.85,-2.25) 30(2.85,2.25)
  rect 0.8x0.3 smd: 2(-2.85,1.75) 3(-2.85,1.25) 4(-2.85,0.75) 5(-2.85,0.25) 6(-2.85,-0.25) 7(-2.85,-0.75) 8(-2.85,-1.25) 9(-2.85,-1.75) 22(2.85,-1.75) 23(2.85,-1.25) 24(2.85,-0.75) 25(2.85,-0.25) 26(2.85,0.25) 27(2.85,0.75) 28(2.85,1.25) 29(2.85,1.75)
  rrect 0.3x0.8 smd: 11(-2.25,-2.85) 20(2.25,-2.85) 31(2.25,2.85) 40(-2.25,2.85)
  rect 0.3x0.8 smd: 12(-1.75,-2.85) 13(-1.25,-2.85) 14(-0.75,-2.85) 15(-0.25,-2.85) 16(0.25,-2.85) 17(0.75,-2.85) 18(1.25,-2.85) 19(1.75,-2.85) 32(1.75,2.85) 33(1.25,2.85) 34(0.75,2.85) 35(0.25,2.85) 36(-0.25,2.85) 37(-0.75,2.85) 38(-1.25,2.85) 39(-1.75,2.85)
  rect 2.8x2.8 smd: 41(0,0)
LQFP_64
  rect 1.65x0.3 smd: 1(-5.65,3.75) 2(-5.65,3.25) 3(-5.65,2.75) 4(-5.65,2.25) 5(-5.65,1.75) 6(-5.65,1.25) 7(-5.65,0.75) 8(-5.65,0.25) 9(-5.65,-0.25) 10(-5.65,-0.75) 11(-5.65,-1.25) 12(-5.65,-1.75) 13(-5.65,-2.25) 14(-5.65,-2.75) 15(-5.65,-3.25) 16(-5.65,-3.75) 33(5.65,-3.75) 34(5.65,-3.25) 35(5.65,-2.75) 36(5.65,-2.25) 37(5.65,-1.75) 38(5.65,-1.25) 39(5.65,-0.75) 40(5.65,-0.25) 41(5.65,0.25) 42(5.65,0.75) 43(5.65,1.25) 44(5.65,1.75) 45(5.65,2.25) 46(5.65,2.75) 47(5.65,3.25) 48(5.65,3.75)
  rect 0.3x1.65 smd: 17(-3.75,-5.65) 18(-3.25,-5.65) 19(-2.75,-5.65) 20(-2.25,-5.65) 21(-1.75,-5.65) 22(-1.25,-5.65) 23(-0.75,-5.65) 24(-0.25,-5.65) 25(0.25,-5.65) 26(0.75,-5.65) 27(1.25,-5.65) 28(1.75,-5.65) 29(2.25,-5.65) 30(2.75,-5.65) 31(3.25,-5.65) 32(3.75,-5.65) 49(3.75,5.65) 50(3.25,5.65) 51(2.75,5.65) 52(2.25,5.65) 53(1.75,5.65) 54(1.25,5.65) 55(0.75,5.65) 56(0.25,5.65) 57(-0.25,5.65) 58(-0.75,5.65) 59(-1.25,5.65) 60(-1.75,5.65) 61(-2.25,5.65) 62(-2.75,5.65) 63(-3.25,5.65) 64(-3.75,5.65)
MH_C350HN350
  round 3.5 hole 3.5 unplated: (0,0)
  round 0.32 smd: 1(0,3)
MH_NP_M3_SO_600
  round 3.4 hole 3.404 unplated: (0,0)
  round 0.43 smd: 1(0.3,-2.6)
MSOP8E65P490X110
  rect 1x0.4 smd: 1(-2.3,0.975) 2(-2.3,0.325) 3(-2.3,-0.325) 4(-2.3,-0.975) 5(2.3,-0.975) 6(2.3,-0.325) 7(2.3,0.325) 8(2.3,0.975)
  rect 1.9x2.54 smd: 9(0,0)
OSC_330X260X120_4_RAL
  rect 1.4x1.2 smd: 1(-1.1,-0.8) 2(1.1,-0.8) 3(1.1,0.8) 4(-1.1,0.8)
OSC_RAL_500X320X154
  rect 0.89x1.41 smd: 1(-1.27,-0.935) 2(0,-0.935) 3(1.27,-0.935) 4(1.27,0.935) 5(0,0.935) 6(-1.27,0.935)
PC_1935174
  rect 2.3x2.3 hole 1.3: 1(0,0)
  round 2.3 hole 1.3: 2(5,0) 3(10,0)
PQFN10_MP5016HGQH
  custom 0.188x0.188 smd: 1-2(-0.4,0) 6-7(0.4,0)
  rect 0.25x0.7 smd: 3(-0.5,-0.975) 4(0,-0.975) 5(0.5,-0.975) 8(0.5,1.025) 9(0,1.025) 10(-0.5,1.025)
PQFN20_MPS_MPM3840GQV
  rrect 0.8x0.25 smd: 1(-1.4,1.55)
  rect 0.9x0.25 smd: 2(-1.35,0.9) 11(1.35,0.9)
  rect 1.1x0.25 smd: 3(-1.25,0.25) 10(1.25,0.25)
  custom 0.275x0.275 smd: 4-6(-1,-1.25) 7-9(1,-1.25)
  rect 0.8x0.25 smd: 12(1.4,1.55)
  rect 0.25x0.7 smd: 13(1.25,2.45) 14(0.75,2.45) 17(-0.75,2.45) 18(-1.25,2.45)
  rect 0.25x1.1 smd: 15(0.25,2.25) 16(-0.25,2.25)
  oval 0.15x0.25 smd: 19(0.2,0.575) 20(-0.2,0.575)
PQFN_65P210X2110X100-8
  rect 0.43x0.35 smd: 1(-0.965,0.65) 2(-0.965,0) 3(-0.965,-0.65) 4(0.965,-0.65) 5(0.965,0) 6(0.965,0.65)
  rrect 1.2x1 smd: 7(0,0.305)
  rect 0.912x0.357 smd: 8(0.005,-0.785)
QFN05P500X500X100_32P_330EP
  rrect 0.72x0.26 smd: 1(-2.451,1.75) 2(-2.451,1.25) 3(-2.451,0.75) 4(-2.451,0.25) 5(-2.451,-0.25) 6(-2.451,-0.75) 7(-2.451,-1.25) 8(-2.451,-1.75) 17(2.451,-1.75) 18(2.451,-1.25) 19(2.451,-0.75) 20(2.451,-0.25) 21(2.451,0.25) 22(2.451,0.75) 23(2.451,1.25) 24(2.451,1.75)
  rrect 0.26x0.72 smd: 9(-1.75,-2.451) 10(-1.25,-2.451) 11(-0.75,-2.451) 12(-0.25,-2.451) 13(0.25,-2.451) 14(0.75,-2.451) 15(1.25,-2.451) 16(1.75,-2.451) 25(1.75,2.451) 26(1.25,2.451) 27(0.75,2.451) 28(0.25,2.451) 29(-0.25,2.451) 30(-0.75,2.451) 31(-1.25,2.451) 32(-1.75,2.451)
  rect 3.3x3.3 smd: 33(0,0)
QFN05P600X600X85-36_410
  oval 0.9x0.28 smd: 1(-2.8,2) 2(-2.8,1.5) 3(-2.8,1) 4(-2.8,0.5) 5(-2.8,0) 6(-2.8,-0.5) 7(-2.8,-1) 8(-2.8,-1.5) 9(-2.8,-2) 19(2.8,-2) 20(2.8,-1.5) 21(2.8,-1) 22(2.8,-0.5) 23(2.8,0) 24(2.8,0.5) 25(2.8,1) 26(2.8,1.5) 27(2.8,2)
  oval 0.28x0.9 smd: 10(-2,-2.8) 11(-1.5,-2.8) 12(-1,-2.8) 13(-0.5,-2.8) 14(0,-2.8) 15(0.5,-2.8) 16(1,-2.8) 17(1.5,-2.8) 18(2,-2.8) 28(2,2.8) 29(1.5,2.8) 30(1,2.8) 31(0.5,2.8) 32(0,2.8) 33(-0.5,2.8) 34(-1,2.8) 35(-1.5,2.8) 36(-2,2.8)
  rect 4.1x4.1 smd: 37(0,0)
QFN12_MPM3805A
  rrect 1.05x0.2 smd: 1(-1.025,0.7)
  rect 1.05x0.2 smd: 2(-1.025,0.3) 7(1.025,0.3) 8(1.025,0.7)
  custom 0.263x0.263 smd: 3-4(-1.025,-0.675) 5-6(1.025,-0.675)
  rect 0.2x0.7 smd: 9(0.6,1.45) 10(0.2,1.45) 11(-0.2,1.45) 12(-0.6,1.45)
QFN40P140X180X55-10
  rrect 0.7x0.2 smd: 1(-0.55,0.2)
  rrect 0.6x0.2 smd: 2(-0.6,-0.2) 6(0.6,-0.2) 7(0.6,0.2)
  rrect 0.2x0.6 smd: 3(-0.4,-0.8) 4(0,-0.8) 5(0.4,-0.8) 8(0.4,0.8) 9(0,0.8) 10(-0.4,0.8)
QFN40P300X300X100-16_MP8772
  rect 0.9x0.2 smd: 1(-1.35,1.2) 2(-1.35,0.8) 3(-1.35,0.4) 4(-1.35,0) 5(-1.35,-0.4) 6(-1.35,-0.8) 7(-1.35,-1.2) 9(1.35,-1.2) 10(1.35,-0.8) 11(1.35,-0.4) 12(1.35,0) 13(1.35,0.4) 14(1.35,0.8) 15(1.35,1.2)
  rect 0.25x2.6 smd: 8(-0.275,-0.5) 16(0.275,0.5)
QFN_RSV_16
  rect 0.75x0.2 smd: 1(-0.725,0.6)
  rect 0.65x0.2 smd: 2(-0.775,0.2) 3(-0.775,-0.2) 4(-0.775,-0.6) 9(0.775,-0.6) 10(0.775,-0.2) 11(0.775,0.2) 12(0.775,0.6)
  rect 0.2x0.65 smd: 5(-0.6,-1.175) 6(-0.2,-1.175) 7(0.2,-1.175) 8(0.6,-1.175) 13(0.6,1.175) 14(0.2,1.175) 15(-0.2,1.175) 16(-0.6,1.175)
RESC60X30X26
  rect 0.275x0.33 smd: 1(-0.262,0) 2(0.262,0)
RESC100X50X35
  rect 0.5x0.51 smd: 1(-0.45,0) 2(0.45,0)
RESC100X50X40
  rect 0.5x0.51 smd: 1(-0.45,0) 2(0.45,0)
RESC160X80X65
  rect 0.71x0.81 smd: 1(-0.645,0) 2(0.645,0)
RESC200X125X50
  rect 0.98x1.32 smd: 1(-0.78,0) 2(0.78,0)
RESC200X125X75
  rect 0.98x1.32 smd: 1(-0.78,0) 2(0.78,0)
RESC320X160X70
  rect 1x1.6 smd: 1(-1.6,0) 2(1.6,0)
RESC640X320X70
  rect 3.1x4 smd: 1(-2.2,0) 2(2.2,0)
SOD_123
  rect 1.2x0.7 smd: 1(-1.85,0) 2(1.85,0)
SOIC8P127W390
  rect 1.55x0.6 smd: 1(-2.7,1.905) 2(-2.7,0.635) 3(-2.7,-0.635) 4(-2.7,-1.905) 5(2.7,-1.905) 6(2.7,-0.635) 7(2.7,0.635) 8(2.7,1.905)
SOIC14_SOT23-THIN_14_DUAL
  rect 1.55x0.6 smd: A1(-2.94,3.81) A2(-2.94,2.54) A3(-2.94,1.27) A4(-2.94,0) A5(-2.94,-1.27) A6(-2.94,-2.54) A7(-2.94,-3.81) A8(2.94,-3.81) A9(2.94,-2.54) A10(2.94,-1.27) A11(2.94,0) A12(2.94,1.27) A13(2.94,2.54) A14(2.94,3.81)
  rrect 1.05x0.3 smd: B1(-1.386,1.5) B2(-1.386,1) B3(-1.386,0.5) B4(-1.386,0) B5(-1.386,-0.5) B6(-1.386,-1) B7(-1.386,-1.5) B8(1.386,-1.5) B9(1.386,-1) B10(1.386,-0.5) B11(1.386,0) B12(1.386,0.5) B13(1.386,1) B14(1.386,1.5)
SOIC127P600X175-16
  rect 1.4x0.65 smd: 1(-2.6,4.445) 2(-2.6,3.175) 3(-2.6,1.905) 4(-2.6,0.635) 5(-2.6,-0.635) 6(-2.6,-1.905) 7(-2.6,-3.175) 8(-2.6,-4.445) 9(2.6,-4.445) 10(2.6,-3.175) 11(2.6,-1.905) 12(2.6,-0.635) 13(2.6,0.635) 14(2.6,1.905) 15(2.6,3.175) 16(2.6,4.445)
SOIC127P1283X750X355-20
  rect 1.8x0.6 smd: 1(-4.65,5.715) 2(-4.65,4.445) 3(-4.65,3.175) 4(-4.65,1.905) 5(-4.65,0.635) 6(-4.65,-0.635) 7(-4.65,-1.905) 8(-4.65,-3.175) 9(-4.65,-4.445) 10(-4.65,-5.715) 11(4.65,-5.715) 12(4.65,-4.445) 13(4.65,-3.175) 14(4.65,-1.905) 15(4.65,-0.635) 16(4.65,0.635) 17(4.65,1.905) 18(4.65,3.175) 19(4.65,4.445) 20(4.65,5.715)
SON95P300X300X80-6TP
  rect 0.9x0.4 smd: 1(-1.425,0.95) 2(-1.425,0) 3(-1.425,-0.95) 4(1.425,-0.95) 5(1.425,0) 6(1.425,0.95)
  rect 1.3x2 smd: 7(0,0)
SON127P600X500X100-8TP
  rect 1.37x0.71 smd: 1(-2.758,1.931) 2(-2.758,0.661) 3(-2.758,-0.609) 4(-2.758,-1.879)
  custom 1.11x1.11 smd: 5(0.012,0.026)
SOT23_3
  rect 1.4x0.65 smd: 1(-1.05,0.95) 2(-1.05,-0.95) 3(1.05,0)
SOT23_290X160X110_8
  rect 0.45x1.05 smd: 1(-0.975,-1.3) 2(-0.325,-1.3) 3(0.325,-1.3) 4(0.975,-1.3) 5(0.975,1.3) 6(0.325,1.3) 7(-0.325,1.3) 8(-0.975,1.3)
SOT65P280X280X110-8
  rect 1.1x0.45 smd: 1(-1.325,0.975) 2(-1.325,0.325) 3(-1.325,-0.325) 4(-1.325,-0.975) 5(1.325,-0.975) 6(1.325,-0.325) 7(1.325,0.325) 8(1.325,0.975)
SOT95P251X112-3
  rect 1x1.4 smd: 1(-0.95,-1.1) 2(0.95,-1.1) 3(0,1.1)
SOT95P280X145_5
  rect 0.6x1.2 smd: 1(-0.95,-1.15) 2(0,-1.15) 3(0.95,-1.15) 4(0.95,1.15) 5(-0.95,1.15)
SOT523_1C2C3A
  rect 0.9x0.4 smd: 1(-0.81,0.5) 2(-0.81,-0.5) 3(0.81,0)
SOT_23
  rect 1x1.4 smd: 1(-0.95,-1.1) 2(0.95,-1.1) 3(0,1.1)
STQFN04P400X400X60_32_270
  rect 0.46x0.23 smd: 1(-1.915,1.4) 2(-1.915,1) 3(-1.915,0.6) 4(-1.915,0.2) 5(-1.915,-0.2) 6(-1.915,-0.6) 7(-1.915,-1) 8(-1.915,-1.4) 17(1.915,-1.4) 18(1.915,-1) 19(1.915,-0.6) 20(1.915,-0.2) 21(1.915,0.2) 22(1.915,0.6) 23(1.915,1) 24(1.915,1.4)
  rect 0.23x0.46 smd: 9(-1.4,-1.915) 10(-1,-1.915) 11(-0.6,-1.915) 12(-0.2,-1.915) 13(0.2,-1.915) 14(0.6,-1.915) 15(1,-1.915) 16(1.4,-1.915) 25(1.4,1.915) 26(1,1.915) 27(0.6,1.915) 28(0.2,1.915) 29(-0.2,1.915) 30(-0.6,1.915) 31(-1,1.915) 32(-1.4,1.915)
  rect 1.225x1.225 smd: 33(-0.737,0.737) 34(0.737,0.737) 35(-0.737,-0.737) 36(0.737,-0.737)
SW_OMRON_2P
  rect 0.81x1.7 smd: 1(-1.706,0) 2(1.706,0)
TP_KEY_MINI
  round 1.93 hole 1.168: 1(0,0)
TP_PAD
  round 0.6 smd: 1(0,0)
TP_SM_S2751R
  rect 2.2x1.4 smd: 1(0,0)
TSSOP8_65P440X300MM
  rect 1.55x0.38 smd: 1(-2.875,0.975) 2(-2.875,0.325) 3(-2.875,-0.325) 4(-2.875,-0.975) 5(2.875,-0.975) 6(2.875,-0.325) 7(2.875,0.325) 8(2.875,0.975)
TSSOP8_65P450X310X120
  rrect 1.5x0.45 smd: 1(-2.9,0.975) 2(-2.9,0.325) 3(-2.9,-0.325) 4(-2.9,-0.975) 5(2.9,-0.975) 6(2.9,-0.325) 7(2.9,0.325) 8(2.9,0.975)
TSSOP65P440X500X120_14
  rect 1.5x0.4 smd: 1(-2.938,1.95) 2(-2.938,1.3) 3(-2.938,0.65) 4(-2.938,0) 5(-2.938,-0.65) 6(-2.938,-1.3) 7(-2.938,-1.95) 8(2.938,-1.95) 9(2.938,-1.3) 10(2.938,-0.65) 11(2.938,0) 12(2.938,0.65) 13(2.938,1.3) 14(2.938,1.95)
TSSOP065P620X120_16
  rrect 1.5x0.45 smd: 1(-2.9,2.275) 2(-2.9,1.625) 3(-2.9,0.975) 4(-2.9,0.325) 5(-2.9,-0.325) 6(-2.9,-0.975) 7(-2.9,-1.625) 8(-2.9,-2.275) 9(2.9,-2.275) 10(2.9,-1.625) 11(2.9,-0.975) 12(2.9,-0.325) 13(2.9,0.325) 14(2.9,0.975) 15(2.9,1.625) 16(2.9,2.275)
unnamed#2
  round 1.016 smd: (0,0)
UQFN_8
  rrect 0.55x0.25 smd: 1(-0.675,0.5) 3(-0.675,-0.5) 5(0.675,-0.5) 7(0.675,0.5)
  rrect 0.55x0.2 smd: 2(-0.675,0) 6(0.675,0)
  rrect 0.3x0.6 smd: 4(0,-0.65) 8(0,0.65)
VQFN40P700X700X100-56_460EP
  rect 0.86x0.25 smd: 1(-3.45,2.6) 2(-3.45,2.2) 3(-3.45,1.8) 4(-3.45,1.4) 5(-3.45,1) 6(-3.45,0.6) 7(-3.45,0.2) 8(-3.45,-0.2) 9(-3.45,-0.6) 10(-3.45,-1) 11(-3.45,-1.4) 12(-3.45,-1.8) 13(-3.45,-2.2) 14(-3.45,-2.6) 29(3.45,-2.6) 30(3.45,-2.2) 31(3.45,-1.8) 32(3.45,-1.4) 33(3.45,-1) 34(3.45,-0.6) 35(3.45,-0.2) 36(3.45,0.2) 37(3.45,0.6) 38(3.45,1) 39(3.45,1.4) 40(3.45,1.8) 41(3.45,2.2) 42(3.45,2.6)
  rect 0.25x0.86 smd: 15(-2.6,-3.45) 16(-2.2,-3.45) 17(-1.8,-3.45) 18(-1.4,-3.45) 19(-1,-3.45) 20(-0.6,-3.45) 21(-0.2,-3.45) 22(0.2,-3.45) 23(0.6,-3.45) 24(1,-3.45) 25(1.4,-3.45) 26(1.8,-3.45) 27(2.2,-3.45) 28(2.6,-3.45) 43(2.6,3.45) 44(2.2,3.45) 45(1.8,3.45) 46(1.4,3.45) 47(1,3.45) 48(0.6,3.45) 49(0.2,3.45) 50(-0.2,3.45) 51(-0.6,3.45) 52(-1,3.45) 53(-1.4,3.45) 54(-1.8,3.45) 55(-2.2,3.45) 56(-2.6,3.45)
  rect 4.6x4.6 smd: 57(0,0)
VSON-CLIP11_3X3MM
  rrect 0.6x0.24 smd: 1(-1.4,1) 2(-1.4,0.5) 3(-1.4,0) 4(-1.4,-0.5) 5(-1.4,-1) 6(1.4,-1) 7(1.4,-0.5) 8(1.4,0) 9(1.4,0.5) 10(1.4,1)
  custom 0.412x0.412 smd: 11(0,0)
VSSOP50P490X110-10
  rect 1.4x0.3 smd: 1(-2.2,1) 2(-2.2,0.5) 3(-2.2,0) 4(-2.2,-0.5) 5(-2.2,-1) 6(2.2,-1) 7(2.2,-0.5) 8(2.2,0) 9(2.2,0.5) 10(2.2,1)
XTAL_320X250X71
  rect 1.4x1.1 smd: 1(-1.1,-0.8) 2(1.1,-0.8) 3(1.1,0.8) 4(-1.1,0.8)
XTAL_ABM8
  rect 1.3x1.05 smd: 1(-1.156,-0.94) 2(1.156,-0.94) 3(1.156,0.94) 4(-1.156,0.94)
XTAL_EPSON_FA238
  rect 1.4x1.2 smd: 1(-1.1,-0.8) 2(1.1,-0.8) 3(1.1,0.8) 4(-1.1,0.8)

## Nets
5V0_IN: C3.1 C4.1 C6.1 C26.1 C32.1 C33.1 C34.1 C35.1 C39.1 C43.1 C75.1 C273.1 C311.1 C312.1 C317.1 C598.1 C599.1 C616.1 C786.1 L1.2 L11.1 Q25.2(SOURCE) R4.1 R7.1 R28.1 R30.1 R209.1 R527.1 TP3.1(TP) TP48.1(TP) U1.15(VIN) U3.7(VIN) U5.7(VIN) U7.5 U7.8 U14.1 U14.2 U14.3 U14.12 U19.15(VDD2) U19.31 U37.21 U45.2 U94.A3 U94.A10 U94.B3 U94.B10 U97.7(VIN) U122.8
5V0_IN_EN: R34.2 U6.3
5V0_IN_FB: R32.1 U6.4
5V0_IN_SS: C40.1 U6.6
5V0_IN_SW: C37.2 C319.1 L1.1 U6.16
5V0_IN_VCC: C38.1 Q21.1 R265.1 U6.14
5V0_RS485: C605.1 C606.1 C607.1 L11.2 U95.9
12V_FAN_GND: C209.1 J13.2(P2) L9.1
12V_FAN_PWR: C210.1 J13.1 L8.1
12V_IN: C30.1 C31.1 C36.1 C203.1 C208.1 D2.1(CATHODE) L8.2 Q5.1 Q5.2 Q5.5 Q5.6 Q5.7 Q24.2(SOURCE) R34.1 R526.1 TP2.1(TP) TP49.1(TP) U6.8(VIN)
12V_IN_JACK: C204.1 C205.1 D1.1(CATHODE) J12.1 R133.1 TP1.1(TP) TP47.1(TP) U41.1-2(VCC)
12V_IN_SOURCE: Q5.4 Q5.8(SPAD) U41.6-7
AGND1: U6.5 Z1.2(NET2)
AGND2: U3.11 Z4.2(NET2)
AGND3: U5.11 Z5.2(NET2)
AGND4: U97.11 Z6.2(NET2)
GND: C1.2 C2.2 C3.2 C4.2 C6.2 C7.2 C8.2 C16.2 C17.2 C22.2 C23.2 C24.2 C25.2 C26.2 C28.2 C29.2 C30.2 C31.2 C32.2 C33.2 C34.2 C35.2 C36.2 C38.2 C40.2 C42.2 C43.2 C49.2 C50.2 C51.2 C52.2 C53.2 C64.2 C73.2 C75.2 C78.2 C79.2 C80.2 C81.2 C82.2 C83.2 C84.2 C85.2 C87.2 C89.2 C90.2 C91.2 C92.2 C93.2 C94.2 C95.2 C96.2 C97.2 C98.2 C99.2 C100.2 C101.2 C102.2 C103.2 C104.2 C105.2 C175.2 C176.2 C203.2 C204.2 C205.2 C206.2 C207.2 C209.2 C210.2 C234.2 C235.2 C236.2 C237.2 C238.2 C272.2 C273.2 C274.2 C275.2 C276.2 C277.2 C278.1 C283.2 C284.2 C285.2 C286.2 C289.2 C290.2 C291.2 C292.2 C295.2 C296.2 C297.2 C298.2 C299.2 C300.2 C303.2 C304.2 C311.2 C312.2 C317.2 C323.2 C324.2 C329.2 C344.2 C353.2 C354.2 C369.2 C370.2 C371.2 C372.2 C373.2 C374.2 C375.2 C376.2 C377.2 C378.2 C379.2 C380.2 C387.2 C548.2 C557.2 C558.2 C559.2 C560.2 C561.2 C562.2 C563.2 C564.2 C565.2 C566.2 C567.2 C568.2 C569.2 C574.2 C581.2 C582.2 C589.2 C591.2 C592.2 C598.2 C599.2 C600.2 C601.2 C611.2 C613.2 C614.2 C615.2 C616.2 C617.2 C618.2 C619.2 C620.2 C621.2 C622.2 C623.2 C624.2 C625.2 C626.2 C627.2 C628.2 C629.2 C630.2 C631.2 C632.2 C633.2 C634.2 C635.2 C636.2 C637.2 C638.2 C640.2 C641.2 C642.2 C643.2 C644.2 C645.2 C646.2 C647.2 C648.2 C649.2 C650.2 C651.2 C652.2 C653.2 C654.2 C655.2 C656.2 C657.2 C658.2 C659.2 C660.2 C661.2 C662.2 C663.2 C665.2 C666.2 C667.2 C668.2 C669.2 C670.2 C671.2 C672.2 C673.2 C674.2 C675.2 C676.2 C677.2 C678.2 C679.2 C680.2 C681.2 C682.2 C683.2 C684.2 C685.2 C687.2 C689.2 C690.2 C691.2 C692.2 C693.2 C694.2 C695.2 C697.2 C698.2 C699.2 C700.2 C701.2 C702.2 C704.2 C705.2 C706.2 C707.2 C708.2 C709.2 C710.2 C711.2 C712.2 C713.2 C714.2 C715.2 C716.2 C717.2 C718.2 C719.2 C720.2 C721.2 C722.2 C723.2 C724.2 C725.2 C726.2 C727.2 C728.2 C729.2 C730.2 C731.2 C732.2 C733.2 C734.2 C735.2 C736.2 C737.2 C738.2 C739.2 C740.2 C741.2 C742.2 C743.2 C744.2 C745.2 C746.2 C747.2 C748.2 C749.2 C750.2 C751.2 C752.2 C753.2 C754.2 C755.2 C756.2 C757.2 C758.2 C759.2 C760.2 C761.2 C762.2 C763.2 C764.2 C765.2 C766.2 C767.2 C768.2 C769.2 C770.2 C771.2 C772.2 C773.2 C775.2 C776.2 C777.2 C778.2 C780.2 C781.2 C782.2 C783.2 C784.2 C785.2 C786.2 C787.2 C789.2 C793.2 C794.2 C795.2 C796.2 C797.2 C798.2 C799.2 C800.2 C801.2 C802.2 C803.2 C804.2 C805.2 C806.2 C807.2 C808.2 C809.2 C810.2 C811.2 C812.2 C813.2 C814.2 C815.2 C816.2 C817.2 C818.2 C819.2 C820.2 C821.2 C822.2 C823.2 C824.2 C825.2 C826.2 C827.2 C828.2 C829.2 D1.2 D12.2 D15.3 D16.3 D17.3 D18.3 D19.3 D20.3 D21.2 J2.9(P9) J2.10 J3.1 J3.3 J3.5 J3.7 J3.9(P9) J3.11 J4.6 J4.7 J4.8 J4.9 J4.10 J4.11 J11.6(VSS) J11.9 J11.10 J11.11 J11.12 J11.14 J12.2 J15.1(P1) J16.1(P1) J17.1(P1) J18.3(P3) J23.2(P2) J24.10 J24.15 J24.16 J25.1 J25.2 J25.3 J25.4 J25.P10_L J25.P10_U J39.2 J39.M1 J39.M2 J42.1 J42.6(P06) J43.1 J43.2 J44.2 J45.2 J46.2 J47.3(P3) JA1.A2 JA1.A5 JA1.A8 JA1.A11 JA1.A14 JA1.A18 JA1.A21 JA1.A26 JA1.A33 JA1.A37 JA1.A41 JA1.A45 JA1.A46 JA1.A49 JA1.A50 JA1.A53 JA1.A54 JA1.A57 JA1.A58 JA1.B3 JA1.B6 JA1.B9 JA1.B12 JA1.B15 JA1.B19 JA1.B23 JA1.B27 JA1.B31 JA1.B35 JA1.B39 JA1.B43 JA1.B47 JA1.B48 JA1.B51 JA1.B52 JA1.B55 JA1.B56 JA1.B59 JA1.C1 JA1.C2 JA1.C5 JA1.C8 JA1.C11 JA1.C14 JA1.C17 JA1.C21 JA1.C25 JA1.C29 JA1.C33 JA1.C37 JA1.C41 JA1.C46 JA1.C49 JA1.C50 JA1.C53 JA1.C54 JA1.C57 JA1.C58 JA1.D3 JA1.D6 JA1.D9 JA1.D12 JA1.D15 JA1.D19 JA1.D23 JA1.D27 JA1.D31 JA1.D35 JA1.D39 JA1.D43 JA1.D47 JA1.D48 JA1.D51 JA1.D52 JA1.D55 JA1.D56 JA1.D59 JA3.A3 JA3.A6 JA3.A9 JA3.B1 JA3.B4 JA3.B7 JA3.B10 JA3.C3 JA3.C6 JA3.C9 JA3.D1 JA3.D4 JA3.D7 JA3.D10 L5.1 L13.1 MH1.1 MH2.1 MH3.1 MH4.1 MH5.1 MH6.1 MH7.1 MH8.1 MH9.1 MH10.1 Q6.2(SOURCE) Q7.2(SOURCE) Q8.2(SOURCE) Q9.2(SOURCE) Q10.2(SOURCE) Q12.2(SOURCE) Q13.2(SOURCE) Q17.2(SOURCE) Q18.2(SOURCE) Q19.2(SOURCE) Q20.2(SOURCE) Q22.2(SOURCE) Q23.2(SOURCE) Q26.2(SOURCE) Q27.2(SOURCE) Q28.2(SOURCE) Q29.2(SOURCE) Q30.2(SOURCE) Q31.2(SOURCE) Q32.2(SOURCE) Q33.2(SOURCE) Q34.2(SOURCE) Q36.1 Q36.2 Q36.3(S3) Q37.2(SOURCE) Q39.1 Q39.2 Q39.3(S3) Q41.1 Q41.2 Q41.3(S3) Q42.1 Q42.2 Q42.3(S3) Q43.2(SOURCE) Q44.2(SOURCE) Q45.2(SOURCE) Q46.2(SOURCE) Q47.2(SOURCE) Q48.2(SOURCE) R2.2 R5.2 R16.2 R17.2 R23.2 R26.2 R29.2 R31.2 R38.2 R41.2 R44.2 R50.2 R51.2 R79.1 R134.2 R135.2 R162.2 R163.2 R165.2 R167.2 R213.2 R219.2 R221.2 R222.2 R223.2 R241.2 R261.2 R262.2 R263.2 R428.2 R462.2 R465.2 R473.2 R474.2 R514.2 R523.2 R525.2 R532.2 R539.2 R552.2 R553.2 R554.2 R555.2 R556.2 R557.2 R558.2 R559.2 R560.2 R566.2 R581.2 R582.2 R583.2 R584.2 R585.2 R586.2 R587.2 R588.2 R589.2 R590.2 R595.2 R608.2 R609.2 R610.2 R611.2 R612.2 R613.2 R614.2 R615.2 R616.2 R623.2 R624.2 R625.2 R630.2 R631.2 R636.2 R637.2 R642.2 R648.2 R652.2 R661.2 R668.2 R675.1 R679.2 R681.2 R682.2 R685.2 R731.1 R733.1 R735.1 R737.1 R761.2 R763.2 SW1.1 SW2.1 U1.1 U1.2 U1.3 U1.17 U1.18 U3.1 U3.2 U5.1 U5.2 U6.9 U6.10 U6.11 U6.12 U6.13 U7.6 U7.9 U8.6 U8.9 U9.6 U9.9 U11.6 U11.9 U12.6 U12.9 U13.5 U13.11 U14.4 U14.5 U14.6 U14.11 U15.2 U15.3 U15.4 U16.1 U19.14 U19.30 U19.33 U19.34 U19.35 U19.36 U22.5 U22.10 U22.11 U22.16 U24.1 U24.5 U24.10 U24.11 U24.13 U24.15 U24.25 U24.35 U24.47 U24.51 U25.1 U25.3 U26.5(VSS) U37.23 U37.33 U38.28 U38.37 U41.3 U42.2 U43.57 U44.4 U44.7 U44.13 U44.16 U44.19 U44.20 U44.21 U44.22 U45.1 U45.9 U64.1 U64.2 U64.3 U66.3 U66.8 U67.3 U67.8 U82.4 U89.3 U91.4 U92.2 U94.A2 U94.A9 U94.B2 U94.B9(WAKE_B) U96.6 U96.9 U97.1 U97.2 U98.5 U98.41 U99.5 U99.41 U100.1 U100.3 U100.4 U101.5 U101.41 U102.9(VSS) U103.9(VSS) U104.9(VSS) U105.2 U105.4 U106.2 U106.4 U107.2 U107.4 U108.4 U108.5 U108.11 U108.12 U109.1 U109.4 U109.10 U109.11 U109.16 U110.4 U110.5 U110.11 U110.12 U111.1 U111.10 U111.11 U111.16 U112.4 U112.5 U112.11 U112.12 U113.2 U113.3 U113.4 U113.7 U114.4 U114.5 U114.11 U114.12 U115.1 U115.4 U115.10 U115.11 U115.16 U116.3 U116.7 U117.4 U117.8 U118.1 U118.2 U118.3 U119.12 U120.1 U120.2 U120.3 U120.10 U121.1 U121.2 U121.3 U121.7 U122.6 U122.9 U123.4 U124.4 U125.4 U127.6 U127.9 U128.6 U128.9 U129.6 U129.9 U130.6 U130.9 U131.6 U131.9 U132.6 U132.9 U133.6 U133.9 U134.6 U134.9 U135.4 U136.4 U137.4 X1.4 X2.2 X2.4 X5.4 X6.4 X11.2 X11.4 X12.2 X12.4 X13.2 X13.4 X14.2 X14.4 Z1.1 Z4.1 Z5.1 Z6.1
GND1_RS485: C602.2 C605.2 C606.2 C607.2 L13.2 U95.6 U95.10
GND2_RS485: C608.2 C609.2 C610.2 L14.1 U95.11
VCC_BATT: C621.1 JA1.A1 R44.1
VCCOEN_PL_M2C: JA1.A20 Q26.1 Q27.1 U3.9 U97.9 U122.5
VCCOEN_PS_M2C: JA1.A19 U1.12 U5.9
A_RS485: D22.1 J22.1 R520.2 U95.20
B_RS485: D22.2(CATHODE2) J21.1 J22.2 U95.19
BRK_CTL_CONN: J46.1 Q42.5
BRK_GATE: Q42.4 R678.2
BRK_GATE_S: R678.1 R679.1 U121.5
CAN_CANH: J18.2 J20.1 U94.A13 U94.B13
CAN_CANL: J18.1 J19.1 U94.A12 U94.B12
CAN_EN: R516.2 U94.A6 U94.B6
CAN_INH: R514.1 U94.A7 U94.B7
CAN_STB_B: R515.2 U94.A14 U94.B14
CC_PL_PGOOD: Q10.1 Q43.1 R28.2 U3.8 U8.3(PG) U9.3(PG) U19.25 U97.8 U122.3(PG)
CC_PS_PGOOD: Q8.1 R7.2 U1.14 U5.8 U12.3(PG) U19.24 U96.3(PG)
CC_PS_POR_B: R452.1 SW2.2(SW2)
CC_PS_POR_B_R: C548.1 R452.2 U19.23
DC_LINK: C689.1 C690.1 C691.1 C697.1 C698.1 C699.1 C704.1 C705.1 C706.1 C748.1 C749.1 C750.1 C751.1 C784.1 J46.3(P3) Q35.5 Q38.5 Q40.5 R531.1 R659.2 R660.1 R761.1 R762.1 U113.1
DCLINK_CONN: F1.1 J39.1
DCLINK_CRNT: C759.1 R663.2 R728.1
DCLINK_CS_B: U114.10 U115.7
DCLINK_CURRENT+: C825.1 R752.2 U114.8
DCLINK_CURRENT-: C824.1 R753.2 U114.7(VINB-)
DCLINK_DATAA: U114.14 U115.8
DCLINK_DATAB: U114.13 U115.9
DCLINK_INPUT: D12.1(CATHODE) F1.3 R659.1 U113.8
DCLINK_SCLK: U114.15 U115.6
DCLINK_VOCM: U133.2(VOCM) U134.2(VOCM) U137.6 U137.7(OUT)
DCLINK_VOCM2: R723.1 R727.1 U137.1 U137.2
DCLINK_VOLT: R724.1 U135.6 U135.7(OUT)
DCLINK_VOLTAGE+: C823.1 R750.2 U114.1
DCLINK_VOLTAGE-: C822.1 R751.2 U114.2
EEPROM_WC_B: Q19.3 R256.1 U15.7(WC_B)
FB_UTIL_3V3: C41.2 R38.1 R39.2 U7.4
FTDI_3V3_FB: C44.2 R36.2 R41.1 U11.4
FTDI_3V3_PG: R40.2 U11.3(PG)
FTDI_EEPROM_WC: Q19.1 R262.1 U24.52
FTDI_LS_OE_B: Q13.1 R235.2 U24.22
FTDI_PS_POR_B: Q46.1 R266.2 U24.23
FTDI_PS_SRST_B: Q48.1 R765.2 U24.24
FTDI_TCK: U22.6 U24.16
FTDI_TDI: U22.7 U24.17
FTDI_TDO: U24.18 U25.9
FTDI_TMS: U24.19 U25.8
FTDI_UARTB_RXD: U24.27 U64.9
FTDI_UARTB_TXD: U24.26 U64.8
FWUEN_C2M_B: C236.1 JA1.C28 SW1.2(SW2)
GEM0_AVDD_3V3: C625.1 C626.1 C634.1 C635.1 C641.1 L15.2 U98.11 U98.20
GEM1_AVDD_3V3: C648.1 C649.1 C658.1 C659.1 C660.1 L16.2 U99.11 U99.20
GEM1_XTAL_IN: R478.2 U99.9
GEM1_XTAL_IN_R: R478.1 U91.8
GEM2_AVDD_3V3: C670.1 C671.1 C680.1 C681.1 C682.1 L17.2 U101.11 U101.20
GEM2_XTAL_IN: R480.2 U101.9
GEM2_XTAL_IN_R: R480.1 U91.7(Y3)
GISOIN_RS485: C603.2 C604.2 D22.3 D23.3 L14.2 U95.14 U95.15
GTR_DP0_C2M_N_NC: JA1.A56
GTR_DP0_C2M_P_NC: JA1.A55
GTR_DP0_M2C_N_NC: JA1.B58
GTR_DP0_M2C_P_NC: JA1.B57
GTR_DP1_C2M_N_NC: JA1.C56
GTR_DP1_C2M_P_NC: JA1.C55
GTR_DP1_M2C_N_NC: JA1.A48
GTR_DP1_M2C_P_NC: JA1.A47
GTR_DP2_C2M_C_N: C309.2 U43.48
GTR_DP2_C2M_C_P: C310.2 U43.47
GTR_DP2_C2M_N: C309.1 JA1.B54
GTR_DP2_C2M_P: C310.1 JA1.B53
GTR_DP2_M2C_C_N: C315.2 U43.51
GTR_DP2_M2C_C_P: C316.2 U43.50
GTR_DP2_M2C_N: C315.1 JA1.D58
GTR_DP2_M2C_P: C316.1 JA1.D57
